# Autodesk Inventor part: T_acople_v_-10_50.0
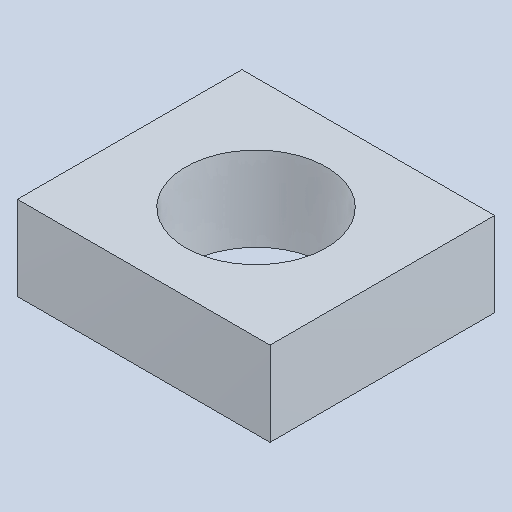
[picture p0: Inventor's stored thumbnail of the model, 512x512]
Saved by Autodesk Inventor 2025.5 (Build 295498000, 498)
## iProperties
Created: 2026-10
Part Number: T_acople_v_-10_50.0
Material: Genérico
Document SubType Name: Modeling
Designer: Luis M
Density: 1 g/cm^3
Appearance: Valor por defecto
Author: Luis M
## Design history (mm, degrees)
feature "Base1"
node "Sólido1"
